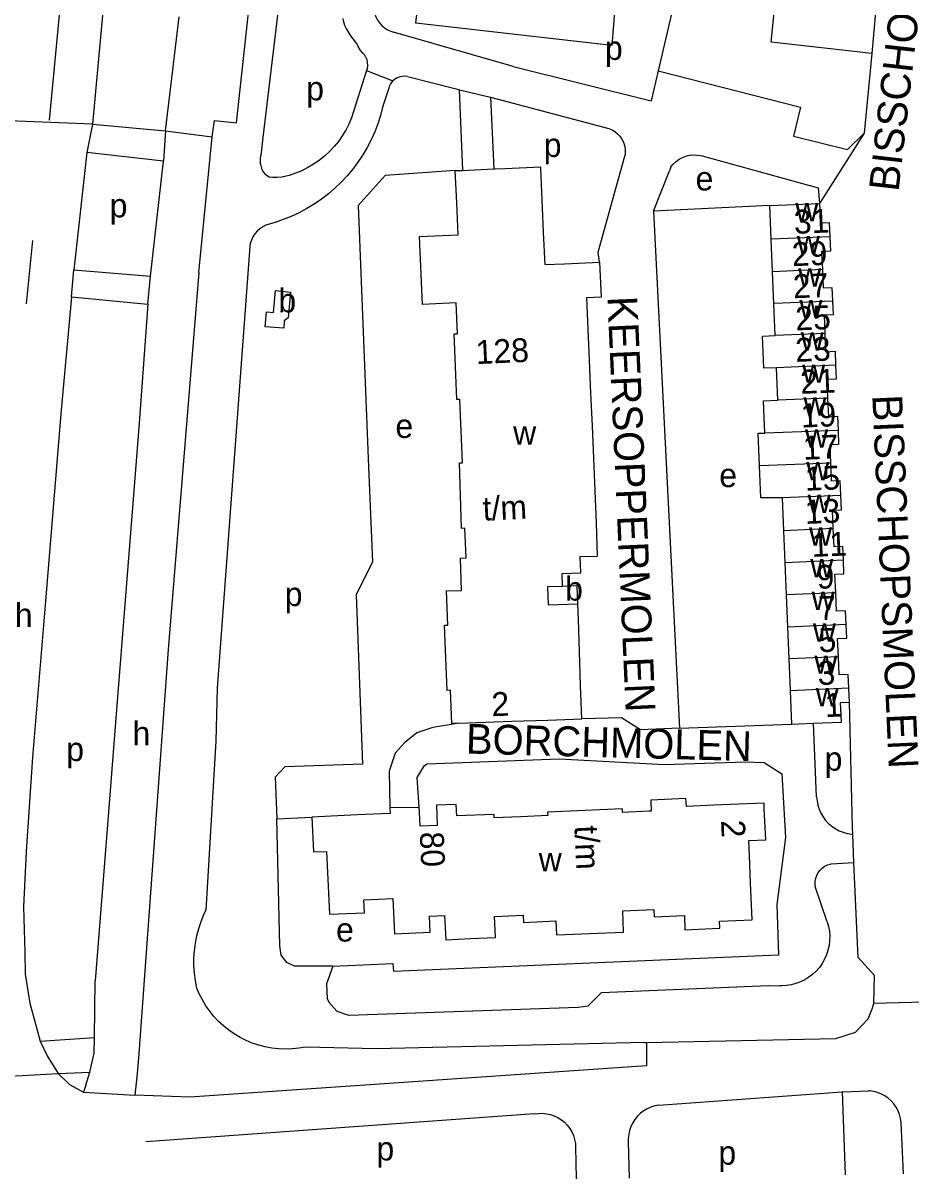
# Model space of a CAD drawing. Extents: x 159902 to 161769, y 383692 to 384875.
# Drawn here: x 161230.6 to 161379.4, y 384130.6 to 384324.5 of the extents above; entities that cross this region are included whole.
import ezdxf

# ---------------------------------------------------------------- set-up
doc = ezdxf.new("R2010")
doc.units = 0
for name, color, linetype in [('BLT_Basislijn', 7, 'Continuous'), ('BLT_Bebouwing', 7, 'Continuous'), ('BLT_Centroide', 7, 'Continuous'), ('BLT_Huisnummer', 7, 'Continuous'), ('BLT_Huisnummer_ tussenligend', 7, 'Continuous'), ('BLT_Huisnummer_reeks', 7, 'Continuous'), ('BLT_Onderverdeling_panden', 7, 'Continuous'), ('BLT_Straatnaam', 7, 'Continuous'), ('BLT_Vlakafsluiter', 7, 'Continuous')]:
    doc.layers.add(name, color=color, linetype=linetype)

msp = doc.modelspace()

# ---------------------------------------------------------------- linework, layer by layer
at = {"layer": 'BLT_Basislijn'}
for p, q in [((161374.02, 384331.65), (161372.88, 384319.36)), ((161339.49, 384326.74), (161337.1, 384316.46)), ((161255.4, 384313.8), (161256.78, 384325.49)), ((161312.77, 384317.16), (161292.73, 384322.94)), ((161372.88, 384319.36), (161371.64, 384305.99)), ((161312.77, 384317.16), (161335.92, 384311.42)), ((161288.22, 384316.49), (161285.67, 384308.56)), ((161288.22, 384316.49), (161292.63, 384314.75)), ((161295.06, 384315.52), (161302.98, 384313.49)), ((161337.1, 384316.46), (161335.92, 384311.42)), ((161254.53, 384306.41), (161255.4, 384313.8)), ((161291.92, 384313.56), (161290.9, 384310.38)), ((161302.98, 384313.49), (161303.81, 384313.29)), ((161303.81, 384313.29), (161308.97, 384312.06)), ((161304.33, 384299.76), (161303.81, 384313.29)), ((161308.97, 384312.06), (161328.82, 384306.77)), ((161308.97, 384312.06), (161309.57, 384299.99)), ((161242.28, 384307.53), (161241.34, 384302.75)), ((161242.28, 384307.53), (161254.53, 384306.41)), ((161254.53, 384306.41), (161254.15, 384301.3)), ((161260.12, 384282.6), (161262.33, 384305.37)), ((161241.34, 384302.75), (161239.12, 384283.08)), ((161254.15, 384301.3), (161241.34, 384302.75)), ((161251.97, 384282), (161254.15, 384301.3)), ((161336.33, 384292.89), (161338.96, 384299.65)), ((161339.22, 384300.34), (161338.96, 384299.65)), ((161355.8, 384293.88), (161336.33, 384292.89)), ((161336.33, 384292.89), (161340.69, 384206.18)), ((161232.2, 384288.01), (161231.15, 384277.36)), ((161238.73, 384278.53), (161239.12, 384283.08)), ((161251.56, 384277.33), (161251.97, 384282)), ((161260.12, 384282.6), (161254.97, 384219.4)), ((161238.73, 384278.53), (161236.98, 384258.94)), ((161238.73, 384278.53), (161251.56, 384277.33)), ((161251.56, 384277.33), (161250.1, 384257.35)), ((161250.1, 384257.35), (161245.87, 384203.62)), ((161254.97, 384219.4), (161250, 384150.86)), ((161369.64, 384189.56), (161369.15, 384210.57)), ((161340.69, 384206.18), (161359.44, 384206.86)), ((161363.65, 384194.69), (161363.1, 384207.02)), ((161262.97, 384204), (161261.27, 384175.65)), ((161273.16, 384190.97), (161279.06, 384191.29)), ((161369.69, 384188.44), (161369.64, 384189.56)), ((161369.54, 384188.43), (161369.69, 384188.44)), ((161369.9, 384183.64), (161369.69, 384188.44)), ((161366.08, 384183.43), (161369.9, 384183.64)), ((161365.41, 384173.71), (161363.47, 384179.48)), ((161357.24, 384168.12), (161292.74, 384165.37)), ((161355.6, 384163.04), (161357.47, 384162.96)), ((161233.52, 384153.68), (161242.59, 384154.31)), ((161334.79, 384153.49), (161335.13, 384153.49)), ((161250, 384150.86), (161249.68, 384147.72)), ((161236.53, 384148.28), (161241.85, 384148.48)), ((161241.16, 384146.29), (161240.79, 384145.12)), ((161249.68, 384147.72), (161249.37, 384144.63)), ((161258.57, 384144.31), (161249.37, 384144.63)), ((161337.2, 384142.97), (161367.9, 384145.2)), ((161367.9, 384145.2), (161368.12, 384145.21)), ((161367.9, 384145.2), (161368.44, 384131.29)), ((161368.12, 384145.21), (161372.33, 384145.35)), ((161316.35, 384141.48), (161262.12, 384137.6)), ((161378.21, 384131.45), (161377.82, 384140.04)), ((161262.12, 384137.6), (161251.21, 384136.82)), ((161332.08, 384136.87), (161332.24, 384130.73)), ((161323.25, 384135.99), (161323.33, 384130.59))]:
    msp.add_line(p, q, dxfattribs=at)
for points in [[(161262.33, 384305.37), (161262.7, 384308.11), (161266.42, 384307.7), (161268.65, 384328.26), (161265, 384328.62), (161268.94, 384362.86), (161276.08, 384424.55)], [(161246.47, 384390.06), (161245.28, 384373.6), (161245.45, 384358.6), (161245.06, 384342.19), (161244.91, 384336.11), (161242.28, 384307.53)], [(161240.93, 384370.62), (161238.81, 384348.25), (161235.01, 384308.19)], [(161372.88, 384319.36), (161356.05, 384321.28), (161357.12, 384332.46), (161357.23, 384333.57)], [(161293.42, 384331.7), (161292.83, 384331.6), (161292.26, 384331.42), (161291.72, 384331.17), (161291.21, 384330.85), (161290.76, 384330.46), (161290.36, 384330.02), (161290.02, 384329.52), (161289.76, 384328.99), (161289.56, 384328.43), (161289.44, 384327.84), (161289.4, 384327.24), (161289.45, 384326.65), (161289.57, 384326.06), (161289.77, 384325.5), (161290.04, 384324.97), (161290.38, 384324.48), (161290.78, 384324.03), (161291.24, 384323.65), (161291.74, 384323.33), (161292.29, 384323.08), (161292.73, 384322.94)], [(161329.87, 384327.74), (161329.33, 384320.72), (161296.47, 384324.43), (161297.23, 384331.31)], [(161273.36, 384326.24), (161270.83, 384305.27), (161270.5, 384302.24)], [(161284.22, 384325.23), (161284.3, 384324.87), (161284.54, 384324.13), (161284.85, 384323.42), (161285.24, 384322.74), (161285.69, 384322.1)], [(161285.69, 384322.1), (161286.16, 384321.53), (161286.58, 384320.91), (161286.85, 384320.4)], [(161288.06, 384318.81), (161287.92, 384319.06), (161287.66, 384319.34), (161287.24, 384319.81), (161286.85, 384320.4)], [(161288.06, 384318.81), (161288.24, 384318.33), (161288.34, 384317.83), (161288.36, 384317.32), (161288.3, 384316.82), (161288.22, 384316.49)], [(161295.06, 384315.52), (161294.59, 384315.56), (161294.12, 384315.52), (161293.67, 384315.41), (161293.24, 384315.22), (161292.85, 384314.96), (161292.63, 384314.75)], [(161337.1, 384316.46), (161360.97, 384310.37), (161359.75, 384305.51)], [(161292.63, 384314.75), (161292.51, 384314.64), (161292.23, 384314.26), (161292.02, 384313.84), (161291.92, 384313.56)], [(161290.9, 384310.38), (161290.53, 384308.97), (161290.09, 384307.58), (161289.57, 384306.22), (161288.97, 384304.89), (161288.3, 384303.6), (161287.57, 384302.34), (161286.76, 384301.12), (161285.89, 384299.96), (161284.96, 384298.84), (161283.96, 384297.77), (161282.91, 384296.76), (161281.81, 384295.81), (161280.65, 384294.92), (161279.45, 384294.09), (161278.21, 384293.34), (161276.92, 384292.65), (161275.6, 384292.03), (161274.25, 384291.49), (161272.87, 384291.02), (161271.91, 384290.74)], [(161285.67, 384308.56), (161285.23, 384307.52), (161284.71, 384306.51), (161284.13, 384305.54), (161283.48, 384304.61), (161282.76, 384303.73), (161281.99, 384302.9), (161281.15, 384302.14), (161280.27, 384301.43), (161279.34, 384300.78), (161278.36, 384300.21), (161277.35, 384299.7), (161276.3, 384299.27), (161275.23, 384298.91), (161274.76, 384298.78)], [(161328.82, 384306.77), (161329.35, 384306.55), (161329.84, 384306.25), (161330.28, 384305.89), (161330.67, 384305.47), (161331, 384305), (161331.26, 384304.49), (161331.45, 384303.95), (161331.55, 384303.39), (161331.58, 384302.82), (161331.55, 384302.37)], [(161359.75, 384305.51), (161368.83, 384303.26), (161371.64, 384305.99)], [(161270.45, 384300.81), (161270.46, 384301.7), (161270.5, 384302.24)], [(161327.25, 384284.36), (161327.03, 384286.03), (161331.55, 384302.37)], [(161339.22, 384300.34), (161339.62, 384300.82), (161340.08, 384301.24), (161340.59, 384301.61), (161341.14, 384301.9), (161341.72, 384302.13), (161342.33, 384302.28), (161342.96, 384302.35), (161343.58, 384302.33), (161344.2, 384302.24), (161344.48, 384302.18)], [(161344.48, 384302.18), (161363.88, 384296.8), (161364.13, 384294.22)], [(161270.45, 384300.81), (161270.52, 384300.36), (161270.67, 384299.92), (161270.9, 384299.52), (161271.18, 384299.17), (161271.53, 384298.87), (161271.97, 384298.61)], [(161303.09, 384299.71), (161291.32, 384298.89), (161286.8, 384293.85), (161288.54, 384250)], [(161274.76, 384298.78), (161273.99, 384298.63), (161273.21, 384298.56), (161272.43, 384298.57), (161271.97, 384298.61)], [(161271.91, 384290.74), (161271.34, 384290.55), (161270.81, 384290.28), (161270.31, 384289.94), (161269.87, 384289.54), (161269.48, 384289.09), (161269.16, 384288.58), (161268.9, 384288.04), (161268.72, 384287.47), (161268.63, 384286.98)], [(161268.63, 384286.98), (161263.15, 384212.89), (161262.97, 384204)], [(161239.12, 384283.08), (161251.97, 384282)], [(161236.98, 384258.94), (161234.38, 384227.49), (161232.24, 384201.33)], [(161288.54, 384250), (161289.18, 384234.09), (161286.46, 384228.53), (161287.54, 384200.13), (161274.52, 384199.73), (161272.89, 384197.97), (161273.16, 384190.97)], [(161303.74, 384207.05), (161299.3, 384206.33), (161296.61, 384205.43), (161294.58, 384203.75), (161293.01, 384202.02), (161291.99, 384198.99), (161292.13, 384192.9)], [(161340.69, 384206.18), (161334.11, 384205.94), (161330.94, 384207.9), (161324.28, 384207.76)], [(161245.87, 384203.62), (161244.96, 384192.09), (161242.71, 384163.8)], [(161232.24, 384201.33), (161231.16, 384185.53), (161230.71, 384176.24)], [(161297.04, 384192.97), (161296.71, 384197.91), (161297.95, 384199.95), (161298.36, 384200.22), (161320.51, 384201.05), (161338.13, 384200.09), (161351.65, 384200.53), (161354.87, 384200.46), (161357.84, 384198.55), (161358.43, 384187.87), (161356.95, 384176.59), (161357.24, 384168.12)], [(161363.65, 384194.69), (161363.71, 384193.98), (161363.85, 384193.27), (161364.07, 384192.59), (161364.36, 384191.93), (161364.72, 384191.31), (161365.15, 384190.73), (161365.64, 384190.21), (161366.18, 384189.74), (161366.77, 384189.34), (161367.41, 384189), (161368.08, 384188.74), (161368.77, 384188.55), (161369.54, 384188.43)], [(161282.56, 384166.3), (161282.37, 384166.3), (161276.13, 384166.29), (161274.87, 384166.87), (161273.9, 384168.12), (161273.67, 384169.7), (161273.16, 384190.97)], [(161363.47, 384179.48), (161363.4, 384179.99), (161363.41, 384180.51), (161363.5, 384181.01), (161363.67, 384181.5), (161363.92, 384181.96), (161364.23, 384182.37), (161364.59, 384182.73), (161365.02, 384183.03), (161365.48, 384183.26), (161365.97, 384183.41), (161366.08, 384183.43)], [(161373.26, 384160.01), (161373.35, 384164.73), (161370.62, 384167.71), (161369.9, 384183.64)], [(161230.71, 384176.24), (161230.91, 384168.63), (161231.01, 384164.94), (161231.75, 384160.05), (161232.71, 384156.59), (161233.52, 384153.68)], [(161259.76, 384162.61), (161259.52, 384163.85), (161259.36, 384165.1), (161259.28, 384166.36), (161259.28, 384167.62), (161259.36, 384168.87), (161259.52, 384170.12), (161259.76, 384171.36), (161260.08, 384172.58), (161260.47, 384173.78), (161260.94, 384174.95), (161261.27, 384175.65)], [(161365.41, 384173.71), (161365.63, 384172.93), (161365.78, 384172.14), (161365.84, 384171.33), (161365.82, 384170.52), (161365.72, 384169.72), (161365.55, 384168.94), (161365.3, 384168.17), (161364.97, 384167.43), (161364.57, 384166.73), (161364.1, 384166.07), (161363.57, 384165.46), (161362.99, 384164.91), (161362.35, 384164.42), (161361.66, 384163.99), (161360.94, 384163.63), (161360.18, 384163.35), (161359.4, 384163.14), (161358.61, 384163.01), (161357.8, 384162.96), (161357.47, 384162.96)], [(161282.56, 384166.3), (161281.47, 384163.33), (161281.63, 384160.81), (161281.95, 384160.17), (161283.22, 384158.74), (161285.2, 384158.03), (161323.7, 384159.38), (161325.37, 384159.61), (161327.57, 384161.85), (161355.6, 384163.04)], [(161282.56, 384166.3), (161292.6, 384166.74), (161292.74, 384165.37)], [(161242.59, 384154.31), (161242.71, 384163.8)], [(161277.96, 384152.71), (161276.84, 384152.52), (161275.72, 384152.4), (161274.59, 384152.37), (161273.46, 384152.41), (161272.34, 384152.54), (161271.23, 384152.74), (161270.13, 384153.02), (161269.06, 384153.38), (161268.02, 384153.81), (161267.01, 384154.32), (161266.04, 384154.9), (161265.11, 384155.54), (161264.23, 384156.25), (161263.4, 384157.02), (161262.63, 384157.84), (161261.92, 384158.72), (161261.27, 384159.64), (161260.69, 384160.61), (161260.18, 384161.62), (161259.76, 384162.61)], [(161335.13, 384153.49), (161366.88, 384154.12), (161370.16, 384155.23), (161372.3, 384157.46), (161372.98, 384159.09), (161373.26, 384160.01)], [(161241.85, 384148.48), (161242.56, 384151.67), (161242.59, 384154.31)], [(161233.52, 384153.68), (161234.66, 384151.22), (161236.53, 384148.28)], [(161335.13, 384153.49), (161335.13, 384149.57), (161258.57, 384144.31)], [(161334.79, 384153.49), (161289.9, 384152.41), (161277.96, 384152.71)], [(161236.53, 384148.28), (161238.41, 384146.43), (161240.79, 384145.12)], [(161241.16, 384146.29), (161241.85, 384148.48)], [(161377.82, 384140.04), (161377.73, 384140.71), (161377.56, 384141.37), (161377.32, 384142), (161377, 384142.6), (161376.61, 384143.16), (161376.16, 384143.66), (161375.66, 384144.11), (161375.1, 384144.5), (161374.5, 384144.82), (161373.87, 384145.07), (161373.22, 384145.24), (161372.55, 384145.34), (161372.33, 384145.35)], [(161337.2, 384142.97), (161336.53, 384142.84), (161335.88, 384142.63), (161335.25, 384142.35), (161334.66, 384142), (161334.12, 384141.59), (161333.62, 384141.11), (161333.19, 384140.58), (161332.82, 384140), (161332.52, 384139.38), (161332.3, 384138.73), (161332.15, 384138.06), (161332.08, 384137.38), (161332.08, 384136.87)], [(161316.35, 384141.48), (161317.02, 384141.58), (161317.7, 384141.6), (161318.37, 384141.53), (161319.04, 384141.39), (161319.68, 384141.17), (161320.29, 384140.88), (161320.86, 384140.52), (161321.39, 384140.09), (161321.86, 384139.6), (161322.27, 384139.07), (161322.62, 384138.48), (161322.89, 384137.86), (161323.09, 384137.21), (161323.21, 384136.55), (161323.25, 384135.99)]]:
    msp.add_lwpolyline(points, dxfattribs=at)
at = {"layer": 'BLT_Bebouwing'}
for p, q in [((161303.09, 384299.71), (161304.33, 384299.76)), ((161303.33, 384294.32), (161303.09, 384299.71)), ((161304.33, 384299.76), (161306.37, 384299.85)), ((161306.37, 384299.85), (161309.57, 384299.99)), ((161303.57, 384288.92), (161303.33, 384294.32)), ((161317.59, 384294.82), (161317.83, 384289.36)), ((161355.8, 384293.88), (161364.13, 384294.22)), ((161356.04, 384288.2), (161355.8, 384293.88)), ((161297.09, 384288.64), (161303.57, 384288.92)), ((161297.57, 384277.26), (161297.09, 384288.64)), ((161317.83, 384289.36), (161318.07, 384283.96)), ((161356.27, 384282.75), (161356.04, 384288.2)), ((161327.25, 384284.36), (161327.51, 384278.48)), ((161356.49, 384277.4), (161356.27, 384282.75)), ((161327.51, 384278.48), (161325.06, 384278.37)), ((161325.06, 384278.37), (161325.52, 384267.84)), ((161356.71, 384272.05), (161356.49, 384277.4)), ((161325.52, 384267.84), (161325.76, 384262.38)), ((161357.16, 384261.21), (161356.94, 384266.65)), ((161325.76, 384262.38), (161326, 384256.93)), ((161326, 384256.93), (161326.24, 384251.48)), ((161365.88, 384253.69), (161365.99, 384250.65)), ((161326.24, 384251.48), (161326.48, 384246.03)), ((161365.99, 384250.65), (161366.11, 384247.61)), ((161326.48, 384246.03), (161326.72, 384240.58)), ((161357.85, 384244.82), (161358.08, 384239.32)), ((161326.72, 384240.58), (161326.84, 384235.06)), ((161358.08, 384239.32), (161358.3, 384233.95)), ((161324, 384234.96), (161326.84, 384235.06)), ((161358.3, 384233.95), (161358.53, 384228.55)), ((161358.53, 384228.55), (161358.76, 384223.15)), ((161323.89, 384219.11), (161323.71, 384224.41)), ((161358.76, 384223.15), (161358.98, 384217.82)), ((161324.09, 384213.33), (161323.89, 384219.11)), ((161358.98, 384217.82), (161359.21, 384212.46)), ((161324.28, 384207.76), (161324.09, 384213.33)), ((161359.21, 384212.46), (161359.44, 384206.86)), ((161369.15, 384210.57), (161369.05, 384212.88)), ((161303.74, 384207.05), (161312.56, 384207.35)), ((161312.56, 384207.35), (161318.57, 384207.56)), ((161359.44, 384206.86), (161363.1, 384207.02)), ((161292.13, 384192.9), (161297.04, 384192.97)), ((161292.13, 384192.9), (161292.17, 384191.88)), ((161286.62, 384191.63), (161279.06, 384191.29)), ((161292.17, 384191.88), (161286.62, 384191.63)), ((161309.53, 384191.74), (161303.32, 384191.47)), ((161309.53, 384191.74), (161309.55, 384191.14)), ((161314.07, 384191.34), (161309.55, 384191.14)), ((161318.59, 384191.54), (161314.07, 384191.34)), ((161324.85, 384192.38), (161318.56, 384192.11)), ((161318.56, 384192.11), (161318.59, 384191.54)), ((161331.05, 384192.66), (161324.85, 384192.38)), ((161331.05, 384192.66), (161331.08, 384192.05)), ((161335.59, 384192.25), (161331.08, 384192.05)), ((161352.58, 384180.24), (161352.38, 384184.86)), ((161287.78, 384177.42), (161292.62, 384177.63)), ((161292.62, 384177.63), (161292.88, 384171.68)), ((161331.14, 384175.54), (161336.34, 384175.76)), ((161309.65, 384174.61), (161314.45, 384174.83))]:
    msp.add_line(p, q, dxfattribs=at)
for points in [[(161309.57, 384299.99), (161309.76, 384300), (161311.46, 384300.08)], [(161311.46, 384300.08), (161317.35, 384300.34), (161317.36, 384300), (161317.59, 384294.82)], [(161364.13, 384294.22), (161364.27, 384290.94), (161365.77, 384291), (161365.87, 384288.61)], [(161365.87, 384288.61), (161365.97, 384286.22), (161364.49, 384286.16), (161364.62, 384283.1)], [(161318.07, 384283.96), (161321.37, 384284.1), (161327.25, 384284.36)], [(161364.62, 384283.1), (161364.75, 384280.05), (161366.22, 384280.11), (161366.32, 384277.81)], [(161271.2, 384273.53), (161271.43, 384276.04), (161272.64, 384275.93), (161272.97, 384279.58), (161275.47, 384279.35), (161275.07, 384275.03), (161274.42, 384274.49), (161274.36, 384273.28), (161271.2, 384273.53)], [(161303.74, 384207.05), (161302.48, 384207), (161302.29, 384212.54), (161301.73, 384212.52), (161301.28, 384223.46), (161301.81, 384223.48), (161301.61, 384229.21), (161304.14, 384229.3), (161303.96, 384234.72), (161304.88, 384234.75), (161304.71, 384239.72), (161304.12, 384239.7), (161303.79, 384250.69), (161304.31, 384250.71), (161303.85, 384261.32), (161303.36, 384261.3), (161302.89, 384272.32), (161303.43, 384272.34), (161303.21, 384277.51), (161297.57, 384277.26)], [(161366.32, 384277.81), (161366.42, 384275.51), (161364.9, 384275.45), (161365.03, 384272.39)], [(161365.03, 384272.39), (161365.15, 384269.34), (161366.74, 384269.41), (161366.83, 384267.07)], [(161356.94, 384266.65), (161354.79, 384266.55), (161354.56, 384271.97), (161356.71, 384272.05)], [(161366.83, 384267.07), (161366.93, 384264.73), (161365.36, 384264.66), (161365.49, 384261.55)], [(161354.95, 384255.69), (161354.72, 384261.11), (161357.16, 384261.21)], [(161365.49, 384261.55), (161365.62, 384258.44), (161367.13, 384258.51), (161367.23, 384256.13)], [(161354.09, 384250.22), (161353.86, 384255.65), (161354.95, 384255.69)], [(161367.23, 384256.13), (161367.33, 384253.75), (161365.88, 384253.69)], [(161357.85, 384244.82), (161354.32, 384244.8), (161354.09, 384250.22)], [(161367.7, 384245.24), (161367.6, 384247.67), (161366.11, 384247.61)], [(161366.43, 384239.68), (161366.3, 384242.75), (161367.81, 384242.82), (161367.7, 384245.24)], [(161368.13, 384234.37), (161368.03, 384236.67), (161366.56, 384236.61), (161366.43, 384239.68)], [(161324.15, 384232.25), (161324, 384234.96)], [(161366.85, 384228.9), (161366.72, 384232.01), (161368.23, 384232.07), (161368.13, 384234.37)], [(161321.04, 384229.96), (161320.97, 384232.14), (161324.15, 384232.25)], [(161323.62, 384227.05), (161323.52, 384230.05), (161321.04, 384229.96)], [(161368.6, 384223.57), (161368.51, 384225.86), (161366.99, 384225.8), (161366.85, 384228.9)], [(161323.71, 384224.41), (161323.62, 384227.05)], [(161367.3, 384218.17), (161367.17, 384221.22), (161368.7, 384221.28), (161368.6, 384223.57)], [(161369.05, 384212.88), (161368.95, 384215.19), (161367.43, 384215.13), (161367.3, 384218.17)], [(161363.1, 384207.02), (161367.79, 384207.21), (161367.65, 384210.5), (161369.15, 384210.57)], [(161318.57, 384207.56), (161320.04, 384207.61), (161324.28, 384207.76)], [(161297.18, 384189.77), (161297.08, 384192.09), (161297.04, 384192.97)], [(161303.32, 384191.47), (161303.24, 384193.41), (161299.92, 384193.26), (161300.07, 384189.89), (161297.18, 384189.77)], [(161341.75, 384194.4), (161335.84, 384194.13), (161335.92, 384192.26), (161335.59, 384192.25)], [(161346.34, 384193.27), (161341.81, 384193.07), (161341.75, 384194.4)], [(161354.88, 384192.65), (161354.84, 384193.64), (161346.34, 384193.27)], [(161279.06, 384191.29), (161279.32, 384185.45), (161281.5, 384185.51), (161282, 384174.99), (161287.87, 384175.22), (161287.78, 384177.42)], [(161352.38, 384184.86), (161352.27, 384187.33), (161355.11, 384187.46), (161354.88, 384192.65)], [(161347.37, 384173.8), (161352.85, 384174.04), (161352.58, 384180.24)], [(161325.66, 384171.76), (161331.3, 384172), (161331.14, 384175.54)], [(161336.34, 384175.76), (161336.39, 384174.57), (161341.48, 384174.79)], [(161292.88, 384171.68), (161298.87, 384171.95), (161298.75, 384174.66)], [(161298.75, 384174.66), (161301.3, 384174.78), (161301.48, 384170.7), (161305.64, 384170.89)], [(161305.64, 384170.89), (161309.81, 384171.07), (161309.65, 384174.61)], [(161314.45, 384174.83), (161314.5, 384173.62), (161319.92, 384173.85)], [(161319.92, 384173.85), (161320.02, 384171.51), (161325.66, 384171.76)], [(161341.48, 384174.79), (161341.58, 384172.38), (161347.42, 384172.64), (161347.37, 384173.8)]]:
    msp.add_lwpolyline(points, dxfattribs=at)
at = {"layer": 'BLT_Onderverdeling_panden'}
for p, q in [((161365.87, 384288.61), (161356.04, 384288.2)), ((161364.62, 384283.1), (161356.27, 384282.75)), ((161366.32, 384277.81), (161356.49, 384277.4)), ((161365.03, 384272.39), (161356.71, 384272.05)), ((161366.83, 384267.07), (161356.94, 384266.65)), ((161365.49, 384261.55), (161357.16, 384261.21)), ((161367.23, 384256.13), (161354.95, 384255.69)), ((161365.99, 384250.65), (161354.09, 384250.22)), ((161367.7, 384245.24), (161357.85, 384244.82)), ((161366.43, 384239.68), (161358.08, 384239.32)), ((161368.13, 384234.37), (161358.3, 384233.95)), ((161366.85, 384228.9), (161358.53, 384228.55)), ((161368.6, 384223.57), (161358.76, 384223.15)), ((161367.3, 384218.17), (161358.98, 384217.82)), ((161369.05, 384212.88), (161359.21, 384212.46))]:
    msp.add_line(p, q, dxfattribs=at)
msp.add_lwpolyline([(161321.04, 384229.96), (161318.55, 384229.88), (161318.65, 384226.88), (161323.62, 384227.05)], dxfattribs=at)
at = {"layer": 'BLT_Vlakafsluiter'}
for p, q in [((161242.28, 384307.53), (161226.83, 384308.12)), ((161254.53, 384306.41), (161262.33, 384305.37)), ((161371.64, 384305.99), (161364.13, 384294.22)), ((161388.43, 384160.39), (161373.26, 384160.01)), ((161227.46, 384147.75), (161236.53, 384148.28)), ((161240.79, 384145.12), (161249.37, 384144.63))]:
    msp.add_line(p, q, dxfattribs=at)

# ---------------------------------------------------------------- texts
at = {"layer": 'BLT_Centroide'}
for s, p in [('p', (161328.17, 384318.28)), ('p', (161278.1, 384311.5)), ('p', (161317.91, 384302)), ('e', (161343.36, 384296.39)), ('p', (161245.15, 384291.87)), ('w', (161360.08, 384291.22)), ('w', (161360.33, 384285.69)), ('w', (161360.55, 384280.25)), ('b', (161273.43, 384275.94)), ('w', (161360.76, 384274.94)), ('w', (161360.98, 384269.53)), ('w', (161361.22, 384264.12)), ('w', (161361.44, 384258.62)), ('e', (161293.05, 384254.87)), ('w', (161312.78, 384253.75)), ('w', (161361.7, 384253.22)), ('e', (161347.33, 384246.62)), ('w', (161361.91, 384247.75)), ('w', (161362.14, 384242.28)), ('w', (161362.37, 384236.81)), ('w', (161362.58, 384231.47)), ('b', (161321.5, 384227.6)), ('p', (161274.5, 384226.68)), ('w', (161362.8, 384226.03)), ('h', (161229.26, 384223.16)), ('w', (161363.02, 384220.69)), ('w', (161363.26, 384215.31)), ('w', (161363.49, 384209.88)), ('h', (161248.98, 384203.32)), ('p', (161237.88, 384200.67)), ('p', (161364.99, 384199.06)), ('w', (161317.07, 384182.19)), ('e', (161283.1, 384170.4)), ('p', (161289.87, 384133.68)), ('p', (161347.18, 384132.98))]:
    msp.add_text(s, height=4, dxfattribs=at).set_placement(p)
at = {"layer": 'BLT_Huisnummer'}
for s, rotation, p in [('31', 2.3865, (161359.91, 384289.1)), ('25', 2.3942, (161360.15, 384272.9)), ('21', 2.3838, (161360.97, 384262.26)), ('17', 2.3799, (161361.44, 384251.21)), ('13', 2.4404, (161361.74, 384240.44)), ('9', 2.4368, (161363.73, 384229.54)), ('5', 2.438, (161364.04, 384218.92)), ('1', 2.4362, (161365.08, 384208.04))]:
    msp.add_text(s, height=4, rotation=rotation, dxfattribs=at).set_placement(p)
at = {"layer": 'BLT_Huisnummer_ tussenligend'}
for s, rotation, p in [('29', 2.3942, (161359.57, 384283.67)), ('27', 2.3942, (161359.76, 384278.29)), ('23', 2.3838, (161360.14, 384267.62)), ('19', 2.3799, (161361.06, 384256.6)), ('15', 2.4404, (161361.74, 384246.01)), ('11', 2.4368, (161362.86, 384234.91)), ('7', 2.438, (161364.02, 384224.3)), ('3', 2.4362, (161363.87, 384213.41))]:
    msp.add_text(s, height=4, rotation=rotation, dxfattribs=at).set_placement(p)
at = {"layer": 'BLT_Huisnummer_reeks'}
for s, rotation, p in [('128', 2.5837, (161306.59, 384267.25)), ('t/m', 2.5833, (161307.75, 384241)), ('2', 1.9751, (161309.21, 384208.19)), ('t/m', 272.5128, (161323.05, 384189.8)), ('2', 272.5057, (161347.62, 384190.73)), ('80', 272.503, (161297.13, 384188.76))]:
    msp.add_text(s, height=4, rotation=rotation, dxfattribs=at).set_placement(p)
at = {"layer": 'BLT_Straatnaam'}
for s, rotation, p in [('BISSCHOPSMOLEN', 83.4585, (161377.37, 384296.07)), ('KEERSOPPERMOLEN', 272.5317, (161328.57, 384278.56)), ('BISSCHOPSMOLEN', 272.5317, (161372.97, 384262.04)), ('BORCHMOLEN', 358.4693, (161304.82, 384201.94))]:
    msp.add_text(s, height=5, rotation=rotation, dxfattribs=at).set_placement(p)

doc.saveas('drawing.dxf')
